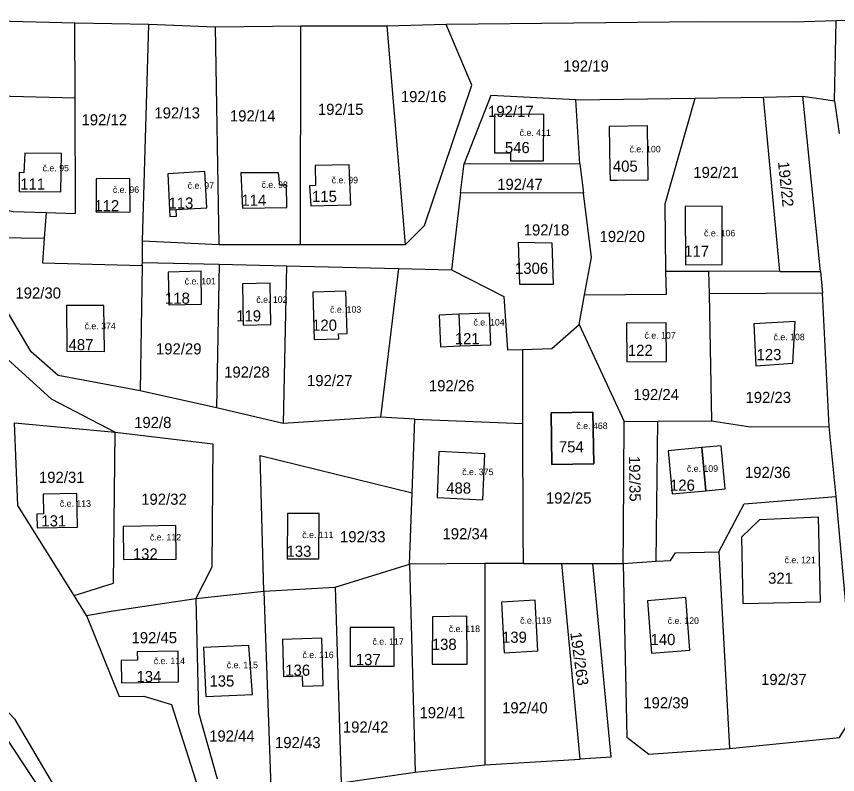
# Model space of a CAD drawing. Extents: x -887272 to -880188, y -1026687 to -1021896.
# Drawn here: x -882525 to -882399.7, y -1024170.3 to -1024054.7 of the extents above; entities that cross this region are included whole.
import ezdxf

# ---------------------------------------------------------------- set-up
doc = ezdxf.new("R2010")
doc.units = 0
for name, color, linetype in [('Definiční body', 7, 'Continuous'), ('Hranice parcel', 7, 'Continuous'), ('Parcelní čísla', 7, 'Continuous'), ('Polygon budovy', 7, 'Continuous'), ('Vnitřní kresba', 7, 'Continuous')]:
    doc.layers.add(name, color=color, linetype=linetype)

msp = doc.modelspace()

# ---------------------------------------------------------------- linework, layer by layer
at = {"layer": 'Hranice parcel'}
for p, q in [((-882516.06, -1024055.78), (-882539.38, -1024055.15)), ((-882516.01, -1024067.18), (-882516.06, -1024055.78)), ((-882504.74, -1024055.95), (-882516.06, -1024055.78)), ((-882400.17, -1024067.6), (-882399.93, -1024055.4)), ((-882376.66, -1024054.74), (-882399.93, -1024055.4)), ((-882505.7, -1024088.95), (-882504.74, -1024055.95)), ((-882494.61, -1024056.37), (-882504.74, -1024055.95)), ((-882481.56, -1024056.23), (-882494.61, -1024056.37)), ((-882494.01, -1024089.53), (-882494.61, -1024056.37)), ((-882481.6, -1024089.53), (-882481.56, -1024056.23)), ((-882468.38, -1024056.21), (-882481.56, -1024056.23)), ((-882459.39, -1024055.99), (-882468.38, -1024056.21)), ((-882465.58, -1024089.52), (-882468.38, -1024056.21)), ((-882516.01, -1024067.18), (-882540.58, -1024066.64)), ((-882421.39, -1024067.22), (-882410.99, -1024067.03)), ((-882410.99, -1024067.03), (-882404.99, -1024066.92)), ((-882408.49, -1024093.61), (-882410.99, -1024067.03)), ((-882404.99, -1024066.92), (-882400.17, -1024067.6)), ((-882439.63, -1024067.48), (-882421.39, -1024067.22)), ((-882439.03, -1024077.2), (-882439.63, -1024067.48)), ((-882400.17, -1024067.6), (-882399.46, -1024072.61)), ((-882457.19, -1024081.63), (-882456.65, -1024077.16)), ((-882456.65, -1024077.16), (-882439.03, -1024077.2)), ((-882439.03, -1024077.2), (-882438.47, -1024081.67)), ((-882457.19, -1024081.63), (-882458.6, -1024093.38)), ((-882438.47, -1024081.67), (-882457.19, -1024081.63)), ((-882520.44, -1024084.62), (-882520.72, -1024088.57)), ((-882533.15, -1024088.37), (-882520.72, -1024088.57)), ((-882505.74, -1024092.24), (-882505.7, -1024088.95)), ((-882505.7, -1024088.95), (-882494.01, -1024089.53)), ((-882494.01, -1024089.53), (-882481.6, -1024089.53)), ((-882481.6, -1024089.53), (-882465.58, -1024089.52)), ((-882505.75, -1024092.74), (-882506.08, -1024111.82)), ((-882505.75, -1024092.74), (-882505.74, -1024092.24)), ((-882505.74, -1024092.24), (-882494.04, -1024092.52)), ((-882494.04, -1024092.52), (-882494.44, -1024114.44)), ((-882494.04, -1024092.52), (-882483.75, -1024092.77)), ((-882483.75, -1024092.77), (-882484.26, -1024116.81)), ((-882483.75, -1024092.77), (-882466.65, -1024093.19)), ((-882466.65, -1024093.19), (-882469.42, -1024115.86)), ((-882466.65, -1024093.19), (-882458.6, -1024093.38)), ((-882425.89, -1024093.57), (-882419.37, -1024093.58)), ((-882419.37, -1024093.58), (-882419.3, -1024097.06)), ((-882408.49, -1024093.61), (-882419.37, -1024093.58)), ((-882419.3, -1024097.06), (-882418.9, -1024116.42)), ((-882439.12, -1024101.73), (-882438.28, -1024097.17)), ((-882439.12, -1024101.73), (-882432.22, -1024116.49)), ((-882447.68, -1024116.83), (-882447.72, -1024105.51)), ((-882494.44, -1024114.44), (-882506.08, -1024111.82)), ((-882484.26, -1024116.81), (-882494.44, -1024114.44)), ((-882469.42, -1024115.86), (-882484.26, -1024116.81)), ((-882464.18, -1024116.13), (-882469.42, -1024115.86)), ((-882464.6, -1024127.37), (-882464.18, -1024116.13)), ((-882464.18, -1024116.13), (-882447.68, -1024116.83)), ((-882432.22, -1024116.49), (-882427.09, -1024116.46)), ((-882427.35, -1024137.82), (-882427.09, -1024116.46)), ((-882427.09, -1024116.46), (-882418.9, -1024116.42)), ((-882399.92, -1024127.96), (-882400.99, -1024117.27)), ((-882465, -1024138.24), (-882464.6, -1024127.37)), ((-882417.8, -1024136.36), (-882416.18, -1024166.34)), ((-882476.32, -1024141.77), (-882465, -1024138.24)), ((-882453.49, -1024138.14), (-882465, -1024138.24)), ((-882465, -1024138.24), (-882464.13, -1024169.99)), ((-882453.49, -1024138.14), (-882453.52, -1024168.83)), ((-882447.61, -1024138.14), (-882453.49, -1024138.14)), ((-882447.61, -1024138.14), (-882441.77, -1024138.13)), ((-882438.97, -1024167.97), (-882441.77, -1024138.13)), ((-882441.77, -1024138.13), (-882437.06, -1024138.13)), ((-882437.06, -1024138.13), (-882432.39, -1024138.13)), ((-882432.39, -1024138.13), (-882427.35, -1024137.82)), ((-882487.23, -1024142.35), (-882476.32, -1024141.77)), ((-882476.32, -1024141.77), (-882475.42, -1024171.58)), ((-882514.25, -1024146.09), (-882516.17, -1024143.02)), ((-882497.59, -1024143.48), (-882487.23, -1024142.35)), ((-882487.23, -1024142.35), (-882486.14, -1024172.29)), ((-882508.92, -1024156.33), (-882500.23, -1024156.21)), ((-882416.18, -1024166.34), (-882399.41, -1024164.66)), ((-882453.52, -1024168.83), (-882438.97, -1024167.97)), ((-882464.13, -1024169.99), (-882453.52, -1024168.83)), ((-882475.42, -1024171.58), (-882464.13, -1024169.99))]:
    msp.add_line(p, q, dxfattribs=at)
for points in [[(-882399.93, -1024055.4), (-882406.36, -1024055.62), (-882420.44, -1024055.54), (-882459.39, -1024055.99)], [(-882465.58, -1024089.52), (-882462.72, -1024086.61), (-882455.48, -1024065.24), (-882459.39, -1024055.99)], [(-882439.63, -1024067.48), (-882452.56, -1024066.78), (-882456.65, -1024077.16)], [(-882408.49, -1024093.61), (-882402.31, -1024093.63), (-882404.99, -1024066.92)], [(-882520.44, -1024084.62), (-882515.93, -1024084.81), (-882516.01, -1024067.18)], [(-882425.89, -1024093.57), (-882425.98, -1024083.3), (-882421.39, -1024067.22)], [(-882452.04, -1024069.67), (-882452.03, -1024075.52), (-882449.56, -1024075.52), (-882449.56, -1024076.75), (-882444.53, -1024076.75), (-882444.5, -1024069.65), (-882452.04, -1024069.67)], [(-882434.39, -1024079.72), (-882433.31, -1024079.71), (-882428.57, -1024079.63), (-882428.71, -1024071.42), (-882434.53, -1024071.52), (-882434.42, -1024078.2), (-882434.39, -1024079.72)], [(-882524.56, -1024081.44), (-882518.16, -1024081.48), (-882518.1, -1024075.64), (-882523.66, -1024075.58), (-882523.8, -1024078.58), (-882524.56, -1024078.52), (-882524.56, -1024081.44)], [(-882473.94, -1024083.48), (-882474.19, -1024077.39), (-882479.39, -1024077.49), (-882479.33, -1024080.54), (-882480.23, -1024080.56), (-882480.04, -1024083.6), (-882473.94, -1024083.48)], [(-882507.66, -1024079.44), (-882512.81, -1024079.48), (-882512.77, -1024084.58), (-882507.62, -1024084.54), (-882507.66, -1024079.44)], [(-882495.9, -1024083.92), (-882496.2, -1024078.39), (-882501.88, -1024078.72), (-882501.59, -1024084.22), (-882501.54, -1024085.24), (-882500.52, -1024085.19), (-882500.58, -1024084.17), (-882495.9, -1024083.92)], [(-882490.46, -1024083.96), (-882483.72, -1024083.86), (-882483.76, -1024080.46), (-882484.76, -1024080.47), (-882485, -1024078.58), (-882490.72, -1024078.6), (-882490.46, -1024083.96)], [(-882536.9, -1024082.1), (-882525.45, -1024084.46), (-882520.44, -1024084.62)], [(-882438.28, -1024097.17), (-882437.23, -1024091.5), (-882438.47, -1024081.67)], [(-882417.29, -1024083.68), (-882422.93, -1024083.73), (-882422.91, -1024092.62), (-882417.28, -1024092.58), (-882417.29, -1024083.68)], [(-882506.08, -1024111.82), (-882518.58, -1024109.48), (-882522.71, -1024105.86), (-882533.15, -1024088.37)], [(-882520.72, -1024088.57), (-882520.99, -1024092.32), (-882505.75, -1024092.74)], [(-882448.14, -1024095.6), (-882448.38, -1024089.18), (-882443.3, -1024089.26), (-882443.1, -1024095.6), (-882448.14, -1024095.6)], [(-882458.6, -1024093.38), (-882450.61, -1024097.46), (-882450.06, -1024105.58), (-882447.72, -1024105.51)], [(-882501.79, -1024093.72), (-882501.71, -1024098.72), (-882496.72, -1024098.62), (-882496.79, -1024093.56), (-882501.79, -1024093.72)], [(-882438.28, -1024097.17), (-882425.81, -1024097.1), (-882425.89, -1024093.57)], [(-882490.39, -1024101.79), (-882486.14, -1024101.72), (-882486.24, -1024095.42), (-882490.49, -1024095.49), (-882490.39, -1024101.79)], [(-882479.73, -1024096.77), (-882479.54, -1024104.02), (-882475.79, -1024103.92), (-882475.81, -1024103.12), (-882474.51, -1024103.09), (-882474.68, -1024096.64), (-882479.73, -1024096.77)], [(-882400.99, -1024117.27), (-882401.99, -1024096.95), (-882419.3, -1024097.06)], [(-882511.53, -1024105.84), (-882511.6, -1024098.82), (-882517.29, -1024098.81), (-882517.24, -1024105.79), (-882511.53, -1024105.84)], [(-882457.28, -1024104.98), (-882452.6, -1024104.8), (-882452.78, -1024099.98), (-882457.45, -1024100.16), (-882460.45, -1024100.28), (-882460.28, -1024105.1), (-882457.28, -1024104.98)], [(-882447.72, -1024105.51), (-882443.26, -1024105.38), (-882439.12, -1024101.73)], [(-882425.8, -1024107.33), (-882425.86, -1024101.46), (-882431.91, -1024101.53), (-882431.83, -1024107.39), (-882425.8, -1024107.33)], [(-882412.16, -1024108), (-882406.54, -1024107.62), (-882406.16, -1024101.24), (-882412.46, -1024101.62), (-882412.16, -1024108)], [(-882529.15, -1024104.45), (-882519.64, -1024113.02), (-882509.9, -1024118.11)], [(-882436.89, -1024122.96), (-882443.29, -1024123.08), (-882443.39, -1024115.2), (-882437.02, -1024115.09), (-882436.89, -1024122.96)], [(-882516.17, -1024143.02), (-882524.72, -1024129.29), (-882525.26, -1024116.69), (-882509.9, -1024118.11)], [(-882447.61, -1024138.14), (-882447.63, -1024133.32), (-882447.68, -1024116.83)], [(-882432.39, -1024138.13), (-882432.35, -1024133.31), (-882432.22, -1024116.49)], [(-882418.9, -1024116.42), (-882412.99, -1024117.3), (-882400.99, -1024117.27)], [(-882516.17, -1024143.02), (-882510.14, -1024141.13), (-882509.9, -1024118.11)], [(-882509.9, -1024118.11), (-882495.01, -1024119.89), (-882495.16, -1024138.72), (-882497.59, -1024143.48)], [(-882425.54, -1024120.96), (-882424.92, -1024127.53), (-882419.79, -1024127.05), (-882416.85, -1024126.78), (-882417.47, -1024120.19), (-882420.41, -1024120.47), (-882425.54, -1024120.96)], [(-882487.23, -1024142.35), (-882487.75, -1024121.7), (-882464.6, -1024127.37)], [(-882453.8, -1024128.42), (-882453.49, -1024121.43), (-882460.5, -1024121.09), (-882460.79, -1024128.11), (-882453.8, -1024128.42)], [(-882520.83, -1024130.58), (-882521.83, -1024130.65), (-882521.8, -1024132.7), (-882515.65, -1024132.6), (-882515.73, -1024127.5), (-882520.88, -1024127.58), (-882520.83, -1024130.58)], [(-882417.8, -1024136.36), (-882413.94, -1024129.03), (-882399.92, -1024127.96)], [(-882399.41, -1024164.66), (-882396.97, -1024160.77), (-882399.92, -1024127.96)], [(-882478.8, -1024137.46), (-882478.76, -1024130.54), (-882483.62, -1024130.51), (-882483.66, -1024137.43), (-882478.8, -1024137.46)], [(-882411.59, -1024131.48), (-882414.33, -1024134.16), (-882414.12, -1024144.27), (-882402.27, -1024143.98), (-882402.59, -1024131.11), (-882411.59, -1024131.48)], [(-882500.57, -1024137.5), (-882500.66, -1024132.35), (-882508.66, -1024132.51), (-882508.62, -1024137.56), (-882500.57, -1024137.5)], [(-882427.35, -1024137.82), (-882425.17, -1024137.68), (-882424.39, -1024136.54), (-882417.8, -1024136.36)], [(-882437.06, -1024138.13), (-882434.29, -1024167.7), (-882438.97, -1024167.97)], [(-882432.39, -1024138.13), (-882431.82, -1024164.63), (-882428.47, -1024167.2), (-882416.18, -1024166.34)], [(-882514.25, -1024146.09), (-882510.19, -1024145.38), (-882497.59, -1024143.48)], [(-882497.59, -1024143.48), (-882497.2, -1024160.85), (-882494.31, -1024171)], [(-882422.22, -1024151.37), (-882422.84, -1024143.36), (-882428.67, -1024143.82), (-882428.08, -1024151.8), (-882422.22, -1024151.37)], [(-882445.82, -1024143.75), (-882450.96, -1024144.04), (-882450.53, -1024151.78), (-882445.44, -1024151.49), (-882445.82, -1024143.75)], [(-882501.82, -1024208.81), (-882505.78, -1024194.82), (-882525.14, -1024161.92), (-882540.14, -1024146.21)], [(-882540.14, -1024146.21), (-882538.86, -1024147.89), (-882532.4, -1024155.87), (-882516.84, -1024179.4), (-882505.08, -1024201.85), (-882501.82, -1024208.81)], [(-882514.25, -1024146.09), (-882509.29, -1024158.43), (-882505.52, -1024158.39), (-882501.29, -1024159.64), (-882495.81, -1024176.89), (-882492.56, -1024176.88)], [(-882456.24, -1024146.16), (-882461.48, -1024146.3), (-882461.51, -1024153.52), (-882456.18, -1024153.5), (-882456.24, -1024146.16)], [(-882474.02, -1024147.92), (-882474.02, -1024153.82), (-882467.32, -1024153.82), (-882467.32, -1024147.92), (-882474.02, -1024147.92)], [(-882484.21, -1024155.38), (-882481.36, -1024155.29), (-882481.31, -1024156.84), (-882478.16, -1024156.74), (-882478.39, -1024149.54), (-882484.36, -1024149.73), (-882484.21, -1024155.38)], [(-882496.06, -1024158.42), (-882488.94, -1024158.14), (-882489.48, -1024150.64), (-882496.4, -1024150.98), (-882496.06, -1024158.42)], [(-882500.23, -1024156.21), (-882500.29, -1024151.52), (-882506.52, -1024151.61), (-882506.5, -1024152.91), (-882508.97, -1024152.94), (-882508.92, -1024156.33)]]:
    msp.add_lwpolyline(points, dxfattribs=at)
at = {"layer": 'Polygon budovy'}
for points in [[(-882444.53, -1024076.75), (-882444.5, -1024069.65), (-882452.04, -1024069.67), (-882452.03, -1024075.52), (-882449.56, -1024075.52), (-882449.56, -1024076.75)], [(-882434.53, -1024071.52), (-882434.42, -1024078.2), (-882434.39, -1024079.72), (-882433.31, -1024079.71), (-882428.57, -1024079.63), (-882428.71, -1024071.42)], [(-882523.66, -1024075.58), (-882523.8, -1024078.58), (-882524.56, -1024078.52), (-882524.56, -1024081.44), (-882518.16, -1024081.48), (-882518.1, -1024075.64)], [(-882480.23, -1024080.56), (-882480.04, -1024083.6), (-882473.94, -1024083.48), (-882474.19, -1024077.39), (-882479.39, -1024077.49), (-882479.33, -1024080.54)], [(-882512.81, -1024079.48), (-882512.77, -1024084.58), (-882507.62, -1024084.54), (-882507.66, -1024079.44)], [(-882495.9, -1024083.92), (-882496.2, -1024078.39), (-882501.88, -1024078.72), (-882501.59, -1024084.22), (-882500.58, -1024084.17)], [(-882490.72, -1024078.6), (-882490.46, -1024083.96), (-882483.72, -1024083.86), (-882483.76, -1024080.46), (-882484.76, -1024080.47), (-882485, -1024078.58)], [(-882422.93, -1024083.73), (-882422.91, -1024092.62), (-882417.28, -1024092.58), (-882417.29, -1024083.68)], [(-882501.79, -1024093.72), (-882501.71, -1024098.72), (-882496.72, -1024098.62), (-882496.79, -1024093.56)], [(-882486.14, -1024101.72), (-882486.24, -1024095.42), (-882490.49, -1024095.49), (-882490.39, -1024101.79)], [(-882479.73, -1024096.77), (-882479.54, -1024104.02), (-882475.79, -1024103.92), (-882475.81, -1024103.12), (-882474.51, -1024103.09), (-882474.68, -1024096.64)], [(-882517.29, -1024098.81), (-882517.24, -1024105.79), (-882511.53, -1024105.84), (-882511.6, -1024098.82)], [(-882457.45, -1024100.16), (-882457.28, -1024104.98), (-882452.6, -1024104.8), (-882452.78, -1024099.98)], [(-882425.86, -1024101.46), (-882431.91, -1024101.53), (-882431.83, -1024107.39), (-882425.8, -1024107.33)], [(-882412.46, -1024101.62), (-882412.16, -1024108), (-882406.54, -1024107.62), (-882406.16, -1024101.24)], [(-882443.39, -1024115.2), (-882443.29, -1024123.08), (-882436.89, -1024122.96), (-882437.02, -1024115.09)], [(-882424.92, -1024127.53), (-882419.79, -1024127.05), (-882420.41, -1024120.47), (-882425.54, -1024120.96)], [(-882460.79, -1024128.11), (-882453.8, -1024128.42), (-882453.49, -1024121.43), (-882460.5, -1024121.09)], [(-882515.65, -1024132.6), (-882515.73, -1024127.5), (-882520.88, -1024127.58), (-882520.83, -1024130.58), (-882521.83, -1024130.65), (-882521.8, -1024132.7)], [(-882478.8, -1024137.46), (-882478.76, -1024130.54), (-882483.62, -1024130.51), (-882483.66, -1024137.43)], [(-882411.59, -1024131.48), (-882414.33, -1024134.16), (-882414.12, -1024144.27), (-882402.27, -1024143.98), (-882402.59, -1024131.11)], [(-882508.66, -1024132.51), (-882508.62, -1024137.56), (-882500.57, -1024137.5), (-882500.66, -1024132.35)], [(-882428.08, -1024151.8), (-882422.22, -1024151.37), (-882422.84, -1024143.36), (-882428.67, -1024143.82)], [(-882450.53, -1024151.78), (-882445.44, -1024151.49), (-882445.82, -1024143.75), (-882450.96, -1024144.04)], [(-882461.48, -1024146.3), (-882461.51, -1024153.52), (-882456.18, -1024153.5), (-882456.24, -1024146.16)], [(-882467.32, -1024147.92), (-882474.02, -1024147.92), (-882474.02, -1024153.82), (-882467.32, -1024153.82)], [(-882484.36, -1024149.73), (-882484.21, -1024155.38), (-882481.36, -1024155.29), (-882481.31, -1024156.84), (-882478.16, -1024156.74), (-882478.39, -1024149.54)], [(-882496.4, -1024150.98), (-882496.06, -1024158.42), (-882488.94, -1024158.14), (-882489.48, -1024150.64)], [(-882508.92, -1024156.33), (-882500.23, -1024156.21), (-882500.29, -1024151.52), (-882506.52, -1024151.61), (-882506.5, -1024152.91), (-882508.97, -1024152.94)]]:
    msp.add_lwpolyline(points, close=True, dxfattribs=at)
at = {"layer": 'Vnitřní kresba'}
for p, q in [((-882501.59, -1024084.22), (-882500.58, -1024084.17)), ((-882402.31, -1024093.63), (-882401.99, -1024096.95)), ((-882457.45, -1024100.16), (-882457.28, -1024104.98)), ((-882420.41, -1024120.47), (-882419.79, -1024127.05))]:
    msp.add_line(p, q, dxfattribs=at)

# ---------------------------------------------------------------- texts
at = {"layer": 'Definiční body'}
for s, p in [('č.e. 411', (-882448.19, -1024072.95)), ('č.e. 100', (-882431.43, -1024075.47)), ('č.e. 95', (-882520.96, -1024078.37)), ('č.e. 99', (-882476.86, -1024080.19)), ('č.e. 96', (-882510.25, -1024081.65)), ('č.e. 97', (-882498.83, -1024081.02)), ('č.e. 98', (-882487.57, -1024080.89)), ('č.e. 106', (-882420.06, -1024088.28)), ('č.e. 101', (-882499.29, -1024095.61)), ('č.e. 102', (-882488.36, -1024098.41)), ('č.e. 103', (-882477.11, -1024099.92)), ('č.e. 104', (-882455.24, -1024101.87)), ('č.e. 374', (-882514.56, -1024102.44)), ('č.e. 107', (-882429.15, -1024103.87)), ('č.e. 108', (-882409.46, -1024104.11)), ('č.e. 468', (-882439.53, -1024117.66)), ('č.e. 109', (-882422.68, -1024124.18)), ('č.e. 375', (-882456.95, -1024124.68)), ('č.e. 113', (-882518.33, -1024129.51)), ('č.e. 111', (-882481.35, -1024134.28)), ('č.e. 112', (-882504.59, -1024134.64)), ('č.e. 121', (-882407.78, -1024138.11)), ('č.e. 119', (-882448.12, -1024147.35)), ('č.e. 120', (-882425.6, -1024147.37)), ('č.e. 118', (-882458.99, -1024148.61)), ('č.e. 117', (-882470.64, -1024150.55)), ('č.e. 116', (-882481.32, -1024152.58)), ('č.e. 114', (-882504, -1024153.5)), ('č.e. 115', (-882492.87, -1024154.12))]:
    msp.add_text(s, height=1, dxfattribs=at).set_placement(p)
at = {"layer": 'Parcelní čísla'}
for s, p in [('192/19', (-882441.54, -1024063.15)), ('192/16', (-882466.32, -1024067.81)), ('192/15', (-882478.97, -1024069.75)), ('192/17', (-882453.01, -1024070.07)), ('192/12', (-882515.03, -1024071.35)), ('192/13', (-882503.91, -1024070.3)), ('192/14', (-882492.39, -1024070.75)), ('546', (-882450.44, -1024075.58)), ('405', (-882433.97, -1024078.42)), ('192/21', (-882421.7, -1024079.38)), ('111', (-882524.38, -1024081.15)), ('192/47', (-882451.62, -1024081.19)), ('114', (-882490.63, -1024083.6)), ('115', (-882479.86, -1024083.03)), ('112', (-882513.07, -1024084.45)), ('113', (-882501.76, -1024084.05)), ('192/18', (-882447.57, -1024088.14)), ('192/20', (-882436.01, -1024089.14)), ('117', (-882423.09, -1024091.39)), ('1306', (-882448.9, -1024093.99)), ('192/30', (-882525.11, -1024097.76)), ('118', (-882502.29, -1024098.55)), ('119', (-882491.43, -1024101.24)), ('120', (-882479.85, -1024102.66)), ('121', (-882458.08, -1024104.71)), ('487', (-882517, -1024105.64)), ('192/29', (-882503.67, -1024106.28)), ('122', (-882431.68, -1024106.5)), ('123', (-882412.05, -1024107.15)), ('192/28', (-882493.27, -1024109.82)), ('192/27', (-882480.63, -1024111.11)), ('192/26', (-882462.04, -1024111.9)), ('192/24', (-882430.84, -1024113.24)), ('192/23', (-882413.74, -1024113.68)), ('192/8', (-882507, -1024117.5)), ('754', (-882442.2, -1024121.21)), ('192/36', (-882413.82, -1024125.12)), ('192/31', (-882521.52, -1024125.86)), ('488', (-882459.39, -1024127.5)), ('126', (-882425.25, -1024127.06)), ('192/32', (-882505.92, -1024129.2)), ('192/25', (-882444.18, -1024129.02)), ('131', (-882521.15, -1024132.5)), ('192/33', (-882475.6, -1024134.92)), ('192/34', (-882459.96, -1024134.47)), ('132', (-882507.19, -1024137.54)), ('133', (-882483.75, -1024137.13)), ('321', (-882410.29, -1024141.24)), ('192/45', (-882507.4, -1024150.31)), ('138', (-882461.59, -1024151.32)), ('139', (-882450.88, -1024150.24)), ('140', (-882428.22, -1024150.59)), ('137', (-882473.18, -1024153.64)), ('134', (-882506.64, -1024156.24)), ('136', (-882483.94, -1024155.27)), ('135', (-882495.51, -1024156.91)), ('192/37', (-882411.36, -1024156.68)), ('192/39', (-882429.33, -1024160.24)), ('192/40', (-882450.87, -1024161)), ('192/41', (-882463.47, -1024161.75)), ('192/42', (-882475.16, -1024163.93)), ('192/44', (-882495.56, -1024165.3)), ('192/43', (-882485.51, -1024166.3))]:
    msp.add_text(s, height=1.7, dxfattribs=at).set_placement(p)
for s, rotation, p in [('192/22', 276, (-882408.79, -1024076.94)), ('192/35', 271, (-882431.53, -1024121.77)), ('192/263', 278, (-882440.48, -1024148.72))]:
    msp.add_text(s, height=1.7, rotation=rotation, dxfattribs=at).set_placement(p)

doc.saveas('drawing.dxf')
